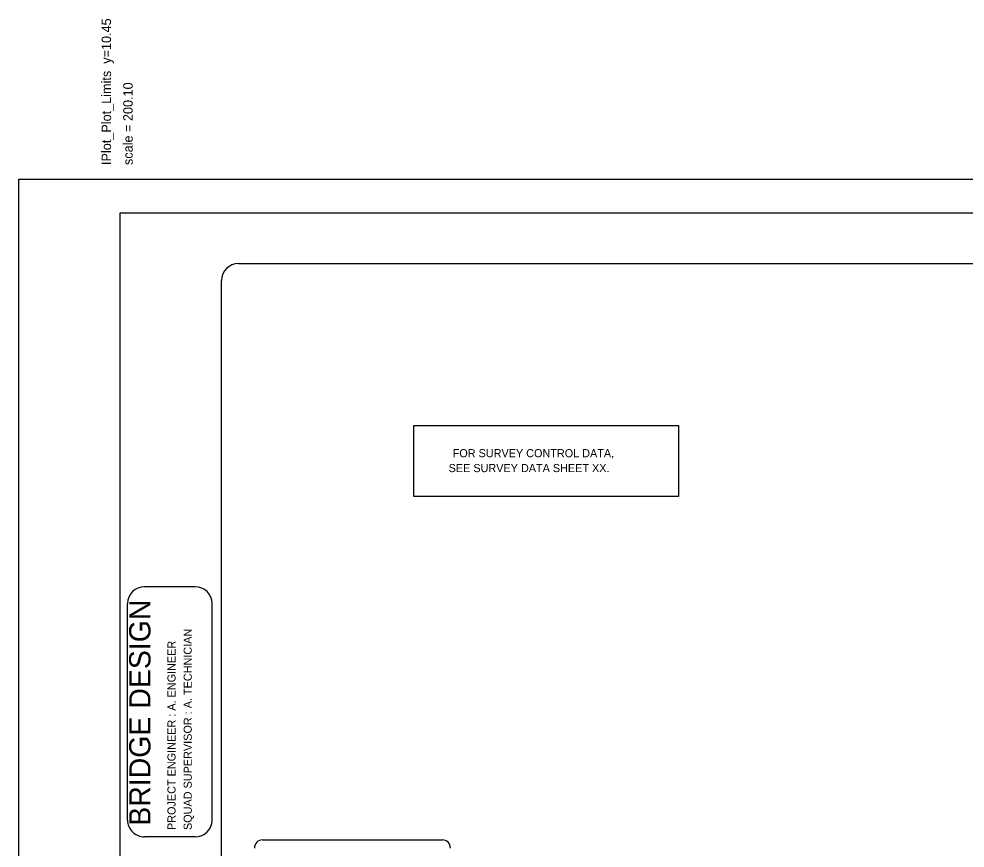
# Model space of a CAD drawing. Extents: x 1458004.1 to 1458040.9, y 194172.7 to 194198.1.
# Drawn here: x 1458004.06 to 1458018.06, y 194185.84 to 194198.11 of the extents above; entities that cross this region are included whole.
import ezdxf

# ---------------------------------------------------------------- set-up
doc = ezdxf.new("R2010")
doc.units = 0
for name, color, linetype in [('Border_0', 7, 'Continuous'), ('Border_9', 7, 'Continuous'), ('IPlot_Plot_Limits', 7, 'Continuous'), ('Plotting_Info', 7, 'Continuous'), ('Text_0', 7, 'Continuous'), ('Text_16', 7, 'Continuous'), ('Text_3', 7, 'Continuous'), ('Text_Box_16', 7, 'Continuous'), ('Text_Box_4', 7, 'Continuous'), ('Text_Box_5', 7, 'Continuous')]:
    doc.layers.add(name, color=color, linetype=linetype)

msp = doc.modelspace()

# ---------------------------------------------------------------- linework, layer by layer
at = {"layer": 'Border_0'}
for p, q in [((1458005.56, 194173.238), (1458005.56, 194195.239)), ((1458005.56, 194195.239), (1458040.06, 194195.239))]:
    msp.add_line(p, q, dxfattribs=at)
at = {"layer": 'Border_9'}
for p, q in [((1458007.31, 194194.489), (1458039.31, 194194.489)), ((1458007.06, 194174.239), (1458007.06, 194194.239))]:
    msp.add_line(p, q, dxfattribs=at)
msp.add_arc((1458007.31, 194194.24), 0.25, 90, 180, dxfattribs=at)
at = {"layer": 'IPlot_Plot_Limits'}
for p, q in [((1458004.06, 194195.739), (1458040.06, 194195.739)), ((1458004.06, 194172.739), (1458004.06, 194195.739))]:
    msp.add_line(p, q, dxfattribs=at)
at = {"layer": 'Text_Box_16'}
msp.add_line((1458007.665, 194185.962), (1458010.327, 194185.962), dxfattribs=at)
for centre, start, end in [((1458007.665, 194185.843), 90, 180), ((1458010.326, 194185.843), 0, 90)]:
    msp.add_arc(centre, 0.12, start, end, dxfattribs=at)
at = {"layer": 'Text_Box_4'}
msp.add_lwpolyline([(1458009.905, 194192.092), (1458013.821, 194192.092), (1458013.821, 194191.042), (1458009.905, 194191.042)], close=True, dxfattribs=at)
at = {"layer": 'Text_Box_5'}
for p, q in [((1458006.668, 194189.708), (1458005.918, 194189.708)), ((1458005.668, 194186.257), (1458005.668, 194189.459)), ((1458006.918, 194186.257), (1458006.918, 194189.459)), ((1458006.668, 194186.007), (1458005.918, 194186.007))]:
    msp.add_line(p, q, dxfattribs=at)
for centre, major_axis, start_param, end_param in [((1458005.918, 194189.459), (0, -0.25), 3.141593, 4.712389), ((1458006.668, 194189.459), (0, 0.25), 4.712389, 6.283185), ((1458005.918, 194186.257), (0, 0.25), 1.570796, 3.141593), ((1458006.668, 194186.257), (0, -0.25), 0, 1.570796)]:
    msp.add_ellipse(centre, major_axis=major_axis, ratio=0.9993, start_param=start_param, end_param=end_param, dxfattribs=at)

# ---------------------------------------------------------------- texts
at = {"layer": 'Plotting_Info'}
for s, p in [('IPlot_Plot_Limits  y=10.45', (1458005.424, 194195.947)), ('scale = 200.10', (1458005.744, 194195.947))]:
    msp.add_text(s, height=0.14, rotation=90, dxfattribs=at).set_placement(p)
at = {"layer": 'Text_0'}
for s, p in [('SQUAD SUPERVISOR : A. TECHNICIAN           ', (1458006.618, 194186.109)), ('PROJECT ENGINEER : A. ENGINEER               ', (1458006.378, 194186.109))]:
    msp.add_text(s, height=0.12, rotation=90, dxfattribs=at).set_placement(p)
at = {"layer": 'Text_16'}
msp.add_text('BRIDGE DESIGN', height=0.315, rotation=90, dxfattribs=at).set_placement((1458006.007, 194186.172))
at = {"layer": 'Text_3'}
for s, p in [('FOR SURVEY CONTROL DATA,', (1458010.48, 194191.624)), ('SEE SURVEY DATA SHEET XX.', (1458010.42, 194191.404))]:
    msp.add_text(s, height=0.12, dxfattribs=at).set_placement(p)

doc.saveas('drawing.dxf')
